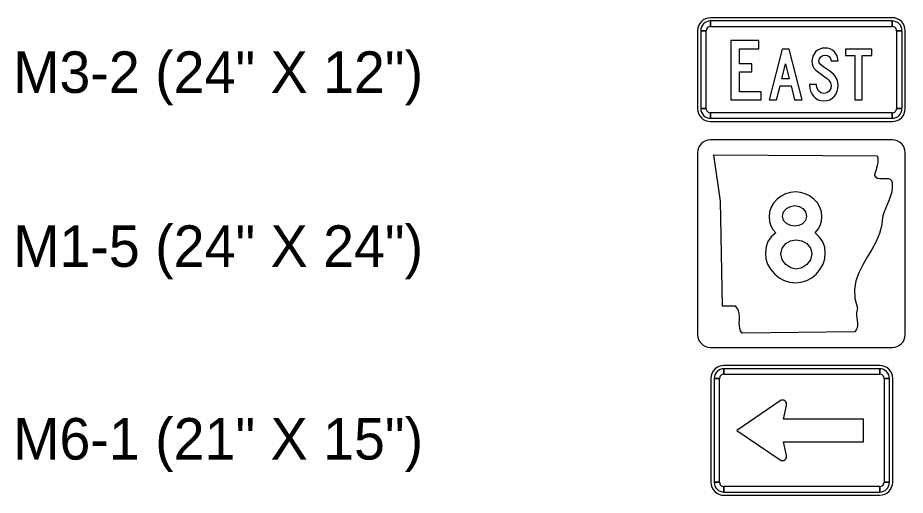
# Model space of a CAD drawing. Extents: x 1001568 to 1002149, y 1840825 to 1841423.
# Drawn here: x 1001996.5 to 1002005.04, y 1841286.47 to 1841291.07 of the extents above; entities that cross this region are included whole.
import ezdxf

# ---------------------------------------------------------------- set-up
doc = ezdxf.new("R2010")
doc.units = 0
doc.layers.add('40', color=7, linetype='Continuous')
doc.layers.add('SIGNS', color=7, linetype='Continuous')

msp = doc.modelspace()

# ---------------------------------------------------------------- linework, layer by layer
at = {"layer": 'SIGNS'}
for p, q in [((1002004.9174, 1841291.0685), (1002003.1674, 1841291.0685)), ((1002003.1674, 1841290.9851), (1002003.1674, 1841291.0372)), ((1002004.9174, 1841291.0372), (1002004.9174, 1841290.9851)), ((1002003.0424, 1841290.9435), (1002003.0424, 1841290.1935)), ((1002003.0737, 1841290.9435), (1002003.1257, 1841290.9435)), ((1002004.9591, 1841290.9435), (1002005.0112, 1841290.9435)), ((1002005.0424, 1841290.1935), (1002005.0424, 1841290.9435)), ((1002003.1257, 1841290.1935), (1002003.0737, 1841290.1935)), ((1002003.1674, 1841290.0997), (1002003.1674, 1841290.1518)), ((1002004.9174, 1841290.1518), (1002004.9174, 1841290.0997)), ((1002005.0112, 1841290.1935), (1002004.9591, 1841290.1935)), ((1002003.1674, 1841290.0685), (1002004.9174, 1841290.0685)), ((1002004.9174, 1841289.8928), (1002003.1674, 1841289.8928)), ((1002003.0424, 1841289.7678), (1002003.0424, 1841288.0178)), ((1002005.0424, 1841288.0178), (1002005.0424, 1841289.7678)), ((1002003.0424, 1841288.0178), (1002003.0424, 1841288.0178)), ((1002003.1674, 1841287.8928), (1002004.9174, 1841287.8928)), ((1002004.7963, 1841287.7191), (1002003.2963, 1841287.7191)), ((1002003.2963, 1841287.6358), (1002003.2963, 1841287.6879)), ((1002004.7963, 1841287.6879), (1002004.7963, 1841287.6358)), ((1002003.1713, 1841287.5941), (1002003.1713, 1841286.5941)), ((1002003.2026, 1841287.5941), (1002003.2547, 1841287.5941)), ((1002004.838, 1841287.5941), (1002004.8901, 1841287.5941)), ((1002004.9213, 1841286.5941), (1002004.9213, 1841287.5941)), ((1002003.8366, 1841287.3793), (1002003.4213, 1841287.0941)), ((1002003.8692, 1841287.2035), (1002003.8994, 1841287.3348)), ((1002004.6401, 1841287.2035), (1002003.8692, 1841287.2035)), ((1002004.6401, 1841287.2035), (1002004.6401, 1841287.2035)), ((1002004.6401, 1841286.9847), (1002004.6401, 1841287.2035)), ((1002003.4213, 1841287.0941), (1002003.4213, 1841287.0941)), ((1002003.4213, 1841287.0941), (1002003.8366, 1841286.8089)), ((1002003.8994, 1841286.8534), (1002003.8692, 1841286.9847)), ((1002003.8692, 1841286.9847), (1002004.6401, 1841286.9847)), ((1002003.2547, 1841286.5941), (1002003.2026, 1841286.5941)), ((1002003.2963, 1841286.5004), (1002003.2963, 1841286.5524)), ((1002004.7963, 1841286.5524), (1002004.7963, 1841286.5004)), ((1002004.8901, 1841286.5941), (1002004.838, 1841286.5941)), ((1002003.2963, 1841286.4691), (1002004.7963, 1841286.4691))]:
    msp.add_line(p, q, dxfattribs=at)
for points in [[(1002004.9174, 1841291.0372), (1002003.1674, 1841291.0372), (1002003.1674, 1841290.9851), (1002004.9174, 1841290.9851), (1002004.9174, 1841291.0372), (1002004.9174, 1841291.0372)], [(1002003.0737, 1841290.9435), (1002003.0737, 1841290.1935), (1002003.1257, 1841290.1935), (1002003.1257, 1841290.9435), (1002003.0737, 1841290.9435), (1002003.0737, 1841290.9435)], [(1002005.0112, 1841290.1935), (1002005.0112, 1841290.9435), (1002004.9591, 1841290.9435), (1002004.9591, 1841290.1935), (1002005.0112, 1841290.1935), (1002005.0112, 1841290.1935)], [(1002003.656, 1841290.3553), (1002003.4453, 1841290.3553), (1002003.4453, 1841290.546), (1002003.5648, 1841290.546), (1002003.5648, 1841290.6245), (1002003.4453, 1841290.6245), (1002003.4453, 1841290.7703), (1002003.6341, 1841290.7703), (1002003.6341, 1841290.8489), (1002003.3617, 1841290.8489), (1002003.3617, 1841290.2768), (1002003.656, 1841290.2768)], [(1002004.1203, 1841290.4241), (1002004.1203, 1841290.4196), (1002004.1224, 1841290.3898), (1002004.1295, 1841290.3621), (1002004.1415, 1841290.3367), (1002004.1583, 1841290.3136), (1002004.1795, 1841290.2932), (1002004.2035, 1841290.2788), (1002004.2299, 1841290.2701), (1002004.2592, 1841290.2672), (1002004.2884, 1841290.2699), (1002004.315, 1841290.2784), (1002004.3386, 1841290.2924), (1002004.3596, 1841290.3122), (1002004.376, 1841290.3349), (1002004.3877, 1841290.36), (1002004.3948, 1841290.3872), (1002004.3972, 1841290.4169), (1002004.3943, 1841290.4453), (1002004.3861, 1841290.4724), (1002004.3723, 1841290.4979), (1002004.3532, 1841290.5221), (1002004.3162, 1841290.554), (1002004.2592, 1841290.593), (1002004.2216, 1841290.6213), (1002004.2135, 1841290.6356), (1002004.2107, 1841290.6519), (1002004.2151, 1841290.6738), (1002004.2283, 1841290.6923), (1002004.2474, 1841290.7048), (1002004.2701, 1841290.709), (1002004.2944, 1841290.705), (1002004.3122, 1841290.6932), (1002004.3217, 1841290.6766), (1002004.329, 1841290.652), (1002004.3972, 1841290.652), (1002004.3861, 1841290.7021), (1002004.3601, 1841290.7415), (1002004.341, 1841290.7568), (1002004.3195, 1841290.7679), (1002004.295, 1841290.7745), (1002004.2681, 1841290.7768), (1002004.2432, 1841290.7744), (1002004.2202, 1841290.7673), (1002004.1989, 1841290.7554), (1002004.1796, 1841290.7389), (1002004.1517, 1841290.6978), (1002004.1425, 1841290.65), (1002004.1448, 1841290.6253), (1002004.1518, 1841290.6028), (1002004.1635, 1841290.5819), (1002004.1801, 1841290.563), (1002004.2597, 1841290.506), (1002004.2893, 1841290.4835), (1002004.3076, 1841290.4668), (1002004.3239, 1841290.4423), (1002004.3294, 1841290.4162), (1002004.3246, 1841290.3872), (1002004.3106, 1841290.3626), (1002004.2875, 1841290.3445), (1002004.2592, 1841290.3385), (1002004.2291, 1841290.3452), (1002004.2058, 1841290.3652), (1002004.1921, 1841290.392), (1002004.1881, 1841290.4241)], [(1002004.5576, 1841290.2768), (1002004.6288, 1841290.2768), (1002004.6288, 1841290.7056), (1002004.7203, 1841290.7056), (1002004.7203, 1841290.7672), (1002004.4681, 1841290.7672), (1002004.4681, 1841290.7056), (1002004.5576, 1841290.7056)], [(1002003.1674, 1841290.0997), (1002004.9174, 1841290.0997), (1002004.9174, 1841290.1518), (1002003.1674, 1841290.1518), (1002003.1674, 1841290.0997), (1002003.1674, 1841290.0997)], [(1002004.7723, 1841289.7384), (1002004.777, 1841289.7194), (1002004.7787, 1841289.6999), (1002004.778, 1841289.6808), (1002004.7757, 1841289.6617), (1002004.7717, 1841289.6426), (1002004.7669, 1841289.6239), (1002004.7613, 1841289.6048), (1002004.7556, 1841289.5865), (1002004.7502, 1841289.5681), (1002004.7452, 1841289.5497), (1002004.7593, 1841289.5336), (1002004.7767, 1841289.5244), (1002004.7964, 1841289.5204), (1002004.8178, 1841289.52), (1002004.8391, 1841289.5207), (1002004.8599, 1841289.5211), (1002004.8789, 1841289.5189), (1002004.8956, 1841289.5127), (1002004.9087, 1841289.5006), (1002004.9167, 1841289.4804), (1002004.9173, 1841289.4348), (1002004.9117, 1841289.3923), (1002004.901, 1841289.3519), (1002004.8866, 1841289.3133), (1002004.8709, 1841289.2751), (1002004.8548, 1841289.2373), (1002004.8398, 1841289.1988), (1002004.8278, 1841289.1591), (1002004.8194, 1841289.1176), (1002004.8174, 1841289.0736), (1002004.7954, 1841288.9914), (1002004.7616, 1841288.9132), (1002004.7208, 1841288.8375), (1002004.6767, 1841288.7626), (1002004.6336, 1841288.6881), (1002004.5958, 1841288.6121), (1002004.5678, 1841288.5336), (1002004.5534, 1841288.451), (1002004.5567, 1841288.3636), (1002004.5825, 1841288.27), (1002004.5748, 1841288.2468), (1002004.5721, 1841288.223), (1002004.5728, 1841288.1991), (1002004.5758, 1841288.1749), (1002004.5792, 1841288.151), (1002004.5818, 1841288.1275), (1002004.5825, 1841288.1044), (1002004.5792, 1841288.0827), (1002004.5708, 1841288.0615), (1002004.5554, 1841288.0416), (1002003.4717, 1841288.0317), (1002003.457, 1841288.0515), (1002003.4487, 1841288.0754), (1002003.445, 1841288.1018), (1002003.4446, 1841288.1301), (1002003.4453, 1841288.1598), (1002003.4456, 1841288.1892), (1002003.4436, 1841288.2182), (1002003.438, 1841288.245), (1002003.4269, 1841288.2692), (1002003.4086, 1841288.2898), (1002003.2822, 1841288.2898), (1002003.2642, 1841289.3016), (1002003.2007, 1841289.7484), (1002004.7723, 1841289.7384), (1002004.7723, 1841289.7384)], [(1002004.7963, 1841287.6879), (1002003.2963, 1841287.6879), (1002003.2963, 1841287.6358), (1002004.7963, 1841287.6358), (1002004.7963, 1841287.6879), (1002004.7963, 1841287.6879)], [(1002003.2026, 1841287.5941), (1002003.2026, 1841286.5941), (1002003.2547, 1841286.5941), (1002003.2547, 1841287.5941), (1002003.2026, 1841287.5941), (1002003.2026, 1841287.5941)], [(1002004.8901, 1841286.5941), (1002004.8901, 1841287.5941), (1002004.838, 1841287.5941), (1002004.838, 1841286.5941), (1002004.8901, 1841286.5941), (1002004.8901, 1841286.5941)], [(1002003.2963, 1841286.5004), (1002004.7963, 1841286.5004), (1002004.7963, 1841286.5524), (1002003.2963, 1841286.5524), (1002003.2963, 1841286.5004), (1002003.2963, 1841286.5004)]]:
    msp.add_lwpolyline(points, close=True, dxfattribs=at)
for points in [[(1002003.7326, 1841290.2768), (1002003.8037, 1841290.2768), (1002003.8369, 1841290.4118), (1002003.9427, 1841290.4118), (1002003.9774, 1841290.2768), (1002004.0491, 1841290.2768), (1002003.9254, 1841290.7672), (1002003.8562, 1841290.7672), (1002003.7326, 1841290.2768)], [(1002003.8542, 1841290.4816), (1002003.8888, 1841290.624), (1002003.9254, 1841290.4816), (1002003.8542, 1841290.4816)], [(1002003.1674, 1841289.8928), (1002003.1674, 1841289.8928)], [(1002004.9174, 1841289.8928), (1002004.9174, 1841289.8928)], [(1002003.0424, 1841289.7678), (1002003.0424, 1841289.7678)], [(1002004.1753, 1841288.9981), (1002004.2037, 1841289.0314), (1002004.224, 1841289.068), (1002004.2364, 1841289.108), (1002004.2406, 1841289.1513), (1002004.2355, 1841289.1991), (1002004.2207, 1841289.2436), (1002004.196, 1841289.2847), (1002004.1617, 1841289.3221), (1002004.1219, 1841289.352), (1002004.0797, 1841289.3734), (1002004.0338, 1841289.3863), (1002003.9849, 1841289.3907), (1002003.9362, 1841289.386), (1002003.8905, 1841289.3729), (1002003.8478, 1841289.3509), (1002003.8081, 1841289.3203), (1002003.7742, 1841289.2834), (1002003.7502, 1841289.2429), (1002003.7359, 1841289.1988), (1002003.7312, 1841289.1513), (1002003.7351, 1841289.1059), (1002003.7472, 1841289.0655), (1002003.7673, 1841289.0294), (1002003.7957, 1841288.9981), (1002003.7518, 1841288.9582), (1002003.7206, 1841288.9122), (1002003.7018, 1841288.8605), (1002003.6957, 1841288.8026), (1002003.7008, 1841288.7465), (1002003.717, 1841288.6943), (1002003.7441, 1841288.6459), (1002003.782, 1841288.6012), (1002003.8272, 1841288.5635), (1002003.8759, 1841288.537), (1002003.9285, 1841288.5211), (1002003.9849, 1841288.516), (1002004.041, 1841288.5211), (1002004.0936, 1841288.537), (1002004.142, 1841288.5635), (1002004.187, 1841288.6012), (1002004.2244, 1841288.6459), (1002004.2512, 1841288.6943), (1002004.2674, 1841288.7465), (1002004.2728, 1841288.8026), (1002004.2666, 1841288.858), (1002004.2483, 1841288.9094), (1002004.2179, 1841288.9561), (1002004.1753, 1841288.9981)], [(1002004.0917, 1841289.1552), (1002004.0822, 1841289.1155), (1002004.0536, 1841289.0843), (1002004.0177, 1841289.0664), (1002003.9777, 1841289.0606), (1002003.9362, 1841289.0664), (1002003.8997, 1841289.0851), (1002003.8702, 1841289.117), (1002003.8607, 1841289.1578), (1002003.8702, 1841289.1991), (1002003.8997, 1841289.2323), (1002003.9362, 1841289.2519), (1002003.9777, 1841289.2586), (1002004.0195, 1841289.2517), (1002004.0559, 1841289.2316), (1002004.0827, 1841289.1975), (1002004.0917, 1841289.1552)], [(1002004.1413, 1841288.7943), (1002004.13, 1841288.7373), (1002004.0961, 1841288.6902), (1002004.0477, 1841288.6584), (1002003.9932, 1841288.6479), (1002003.9391, 1841288.6584), (1002003.8914, 1841288.6904), (1002003.8558, 1841288.7379), (1002003.8441, 1841288.7943), (1002003.8558, 1841288.849), (1002003.8914, 1841288.8929), (1002003.9378, 1841288.9194), (1002003.9932, 1841288.9285), (1002004.0481, 1841288.9194), (1002004.0949, 1841288.8929), (1002004.1296, 1841288.849), (1002004.1413, 1841288.7943)], [(1002003.1674, 1841287.8928), (1002003.1674, 1841287.8928)], [(1002004.9174, 1841287.8928), (1002004.9174, 1841287.8928)]]:
    msp.add_lwpolyline(points, dxfattribs=at)
for centre, radius, start, end in [((1002003.1674, 1841290.9435), 0.125, 90.00021, 179.99985), ((1002003.1674, 1841290.9435), 0.0937, 90.00021, 179.99985), ((1002003.1674, 1841290.9435), 0.0417, 90.00021, 179.99985), ((1002004.9174, 1841290.9435), 0.125, 0, 90.00021), ((1002004.9174, 1841290.9435), 0.0937, 0, 90.00021), ((1002004.9174, 1841290.9435), 0.0417, 0, 90.00021), ((1002003.1674, 1841290.1935), 0.125, 179.99985, 270.00006), ((1002003.1674, 1841290.1935), 0.0937, 179.99985, 270.00006), ((1002003.1674, 1841290.1935), 0.0417, 179.99985, 270.00006), ((1002004.9174, 1841290.1935), 0.125, 270.00006, 0.00027), ((1002004.9174, 1841290.1935), 0.0937, 270.00006, 0.00027), ((1002004.9174, 1841290.1935), 0.0417, 270.00006, 0.00027), ((1002003.1674, 1841289.7678), 0.125, 90.00021, 179.99985), ((1002004.9174, 1841289.7678), 0.125, 0, 90), ((1002003.1674, 1841288.0178), 0.125, 180, 270), ((1002004.9174, 1841288.0178), 0.125, 270.00006, 0.00027), ((1002003.2963, 1841287.5941), 0.125, 90.00006, 180.00027), ((1002003.2963, 1841287.5941), 0.0937, 90.00006, 180.00027), ((1002004.7963, 1841287.5941), 0.125, 359.99985, 90.00006), ((1002004.7963, 1841287.5941), 0.0937, 359.99985, 90.00006), ((1002003.2963, 1841287.5941), 0.0417, 90.00006, 180.00027), ((1002004.7963, 1841287.5941), 0.0417, 359.99985, 90.00006), ((1002003.8588, 1841287.3441), 0.0417, 347.04986, 122.27592), ((1002003.8588, 1841286.8441), 0.0417, 237.72435, 12.95041), ((1002003.2963, 1841286.5941), 0.125, 180, 270.00021), ((1002003.2963, 1841286.5941), 0.0937, 180, 270.00021), ((1002003.2963, 1841286.5941), 0.0417, 180, 270.00021), ((1002004.7963, 1841286.5941), 0.0937, 270.00021, 359.99985), ((1002004.7963, 1841286.5941), 0.0417, 270.00021, 359.99985), ((1002004.7963, 1841286.5941), 0.125, 270.00021, 359.99985)]:
    msp.add_arc(centre, radius, start, end, dxfattribs=at)

# ---------------------------------------------------------------- texts
at = {"layer": '40'}
for s, p in [('M3-2 (24" X 12")', (1001996.4526, 1841290.3445)), ('M1-5 (24" X 24")', (1001996.4526, 1841288.6689)), ('M6-1 (21" X 15")', (1001996.4526, 1841286.8127))]:
    msp.add_text(s, height=0.4, rotation=0, dxfattribs=at).set_placement(p)

doc.saveas('drawing.dxf')
